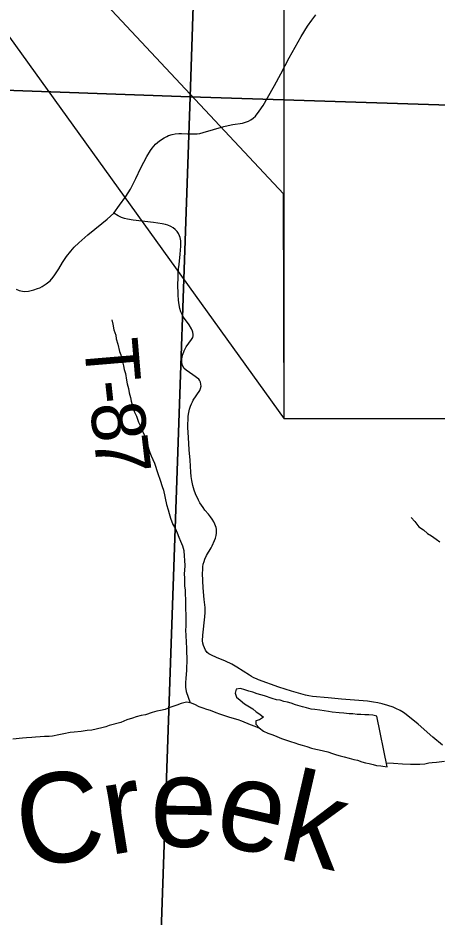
# Model space of a CAD drawing. Extents: x -3.3 to 34, y 0 to 56.8.
# Drawn here: x 0.477 to 0.92, y 29.768 to 30.716 of the extents above; entities that cross this region are included whole.
import ezdxf

# ---------------------------------------------------------------- set-up
doc = ezdxf.new("R2010")
doc.units = 0
for name, color, linetype in [('GM_X_Corporation', 7, 'Continuous'), ('GM_X_Township_Road', 7, 'Continuous'), ('GM_X_Township_Road_Text', 7, 'Continuous'), ('GT_Project_Cells', 7, 'Continuous'), ('GT_Project_Soil_Layers', 7, 'Continuous'), ('SH_Major_Grid_Line', 7, 'Continuous')]:
    doc.layers.add(name, color=color, linetype=linetype)

msp = doc.modelspace()

# ---------------------------------------------------------------- linework, layer by layer
at = {"layer": 'GM_X_Corporation'}
for points in [[(-0.3225, 31.67471), (0.6926, 31.6401), (0.65935, 30.63337), (-0.36109, 30.66979)], [(0.6926, 31.6401), (1.70556, 31.57323), (1.70222, 31.44962), (1.67669, 30.60068), (0.65935, 30.63337)], [(-0.36109, 30.66979), (0.65935, 30.63337), (0.62472, 29.64178), (-0.38619, 29.67495)], [(1.67669, 30.60068), (1.67248, 30.48389), (1.6376, 29.60296), (0.62472, 29.64178), (0.65935, 30.63337)]]:
    msp.add_lwpolyline(points, close=True, dxfattribs=at)
at = {"layer": 'GM_X_Township_Road'}
for points in [[(0.47554, 30.43026), (0.47865, 30.42902), (0.4821, 30.42823), (0.48443, 30.42801), (0.48865, 30.42824), (0.49418, 30.42962), (0.49799, 30.43092), (0.50047, 30.43194), (0.50293, 30.43315), (0.50712, 30.43583), (0.51135, 30.43931), (0.51443, 30.44293), (0.51618, 30.44538), (0.52042, 30.45199), (0.52432, 30.45852), (0.52853, 30.46469), (0.53314, 30.47056), (0.53683, 30.47476), (0.54148, 30.47938), (0.55118, 30.48783), (0.56589, 30.4997), (0.57139, 30.50419), (0.57509, 30.50737), (0.57867, 30.51058), (0.58474, 30.51882), (0.59122, 30.52799), (0.59633, 30.53598), (0.60186, 30.54709), (0.60724, 30.55842), (0.61347, 30.57017), (0.61745, 30.5768), (0.61905, 30.57909), (0.62249, 30.58329), (0.62677, 30.58689), (0.63173, 30.59013), (0.63453, 30.59158), (0.6364, 30.59237), (0.64026, 30.59358), (0.64328, 30.59418), (0.64721, 30.59447), (0.64998, 30.59454), (0.65653, 30.59421), (0.6626, 30.59408), (0.66656, 30.59426), (0.66932, 30.59471), (0.67292, 30.59561), (0.68391, 30.59885), (0.69489, 30.60209), (0.69947, 30.60305), (0.70406, 30.60391), (0.71427, 30.60548), (0.71775, 30.60639), (0.72061, 30.60763), (0.72317, 30.60909), (0.72552, 30.61077), (0.7281, 30.61295), (0.73209, 30.6183), (0.73626, 30.62417), (0.74097, 30.63208), (0.74811, 30.64518), (0.75475, 30.65737), (0.76373, 30.67431), (0.77649, 30.69678), (0.78309, 30.70772), (0.78755, 30.71427), (0.79175, 30.71967)], [(0.92568, 29.94955), (0.91532, 29.95793), (0.89978, 29.97142), (0.88727, 29.98162), (0.88423, 29.98384), (0.88093, 29.98584), (0.87639, 29.98818), (0.87342, 29.98946), (0.86799, 29.99138), (0.86184, 29.99308), (0.85736, 29.9941), (0.85281, 29.99487), (0.84635, 29.99567), (0.819, 29.99801), (0.80494, 29.99927), (0.7884, 30.00076), (0.78437, 30.00133), (0.78091, 30.00207), (0.76604, 30.00619), (0.75288, 30.01062), (0.73142, 30.0183), (0.72913, 30.01925), (0.72656, 30.0205), (0.72379, 30.02197), (0.72169, 30.02324), (0.70849, 30.03175), (0.70332, 30.03471), (0.69633, 30.03816), (0.68696, 30.04203), (0.68153, 30.04441), (0.67882, 30.04589), (0.6771, 30.04728), (0.67545, 30.04975), (0.67414, 30.05205), (0.67323, 30.0546), (0.67266, 30.05715), (0.67233, 30.05937), (0.67241, 30.06537), (0.67463, 30.08485), (0.67496, 30.08937), (0.67488, 30.09447), (0.67413, 30.10302), (0.67304, 30.11537), (0.67223, 30.13063), (0.67239, 30.13465), (0.67257, 30.13746), (0.67307, 30.14042), (0.67387, 30.14329), (0.67464, 30.14569), (0.67644, 30.1493), (0.68136, 30.15771), (0.68243, 30.15978), (0.68493, 30.16537), (0.68583, 30.16777), (0.68663, 30.17042), (0.68701, 30.17318), (0.68713, 30.17519), (0.68689, 30.17737), (0.68647, 30.179), (0.68527, 30.18245), (0.68415, 30.18485), (0.68233, 30.18791), (0.68081, 30.19017), (0.67859, 30.19304), (0.67478, 30.19742), (0.67273, 30.19999), (0.67101, 30.20242), (0.66935, 30.20509), (0.66791, 30.20774), (0.66474, 30.21458), (0.66341, 30.21853), (0.66212, 30.22332), (0.66108, 30.22859), (0.66033, 30.2329), (0.65992, 30.23738), (0.65901, 30.24984), (0.65821, 30.26084), (0.65725, 30.27406), (0.65686, 30.28461), (0.6572, 30.29628), (0.65778, 30.3003), (0.6586, 30.30367), (0.65961, 30.30702), (0.66049, 30.30951), (0.66149, 30.31159), (0.66244, 30.31333), (0.66924, 30.32339), (0.67021, 30.32559), (0.67065, 30.32803), (0.67057, 30.33024), (0.67001, 30.33243), (0.6692, 30.33434), (0.66847, 30.33536), (0.66182, 30.34017), (0.6549, 30.34494), (0.65288, 30.34685), (0.65145, 30.34929), (0.65079, 30.35106), (0.65032, 30.35348), (0.65025, 30.35474), (0.65038, 30.35679), (0.65069, 30.35875), (0.65145, 30.36163), (0.65274, 30.36517), (0.65512, 30.36955), (0.66076, 30.37719), (0.66193, 30.37956), (0.66228, 30.38103), (0.6624, 30.38253), (0.6621, 30.38502), (0.66173, 30.38617), (0.66067, 30.38847), (0.65811, 30.39276), (0.65424, 30.39788), (0.65191, 30.40119), (0.65056, 30.40361), (0.64933, 30.4064), (0.64817, 30.41011), (0.64744, 30.41393), (0.64693, 30.41884), (0.64652, 30.42451), (0.64627, 30.4361), (0.64635, 30.4412), (0.6466, 30.44605), (0.64693, 30.45172), (0.64742, 30.45649), (0.64853, 30.4674), (0.64931, 30.47572), (0.6494, 30.47852), (0.64923, 30.48145), (0.64851, 30.48494), (0.64796, 30.48665), (0.64698, 30.489), (0.64528, 30.49134), (0.64339, 30.4934), (0.6414, 30.49498), (0.6387, 30.49663), (0.63556, 30.49799), (0.633, 30.49872), (0.62965, 30.49935), (0.62038, 30.50063), (0.59904, 30.50332), (0.59313, 30.50418), (0.58989, 30.50495), (0.58669, 30.50611), (0.58316, 30.50787), (0.57867, 30.51058)]]:
    msp.add_lwpolyline(points, dxfattribs=at)
at = {"layer": 'GT_Project_Soil_Layers'}
for points in [[(0.57633, 30.39805), (0.57753, 30.39352), (0.57875, 30.38746), (0.58072, 30.3818), (0.58115, 30.37801), (0.58274, 30.37234), (0.58474, 30.36478), (0.58593, 30.361), (0.58713, 30.35646), (0.58874, 30.34966), (0.58955, 30.3455), (0.59074, 30.34134), (0.59197, 30.33453), (0.59279, 30.33036), (0.59399, 30.32545), (0.59481, 30.3209), (0.59601, 30.31599), (0.59682, 30.31221), (0.59841, 30.30691), (0.6004, 30.30049), (0.60235, 30.29635), (0.60471, 30.28993), (0.60666, 30.28578), (0.60823, 30.28201), (0.61058, 30.27673), (0.61177, 30.27257), (0.61374, 30.26691), (0.61651, 30.25822), (0.61808, 30.25445), (0.61965, 30.25067), (0.62159, 30.2469), (0.62515, 30.23595), (0.62752, 30.22877), (0.62951, 30.22235), (0.63108, 30.2182), (0.63432, 30.20307), (0.63591, 30.19778), (0.6371, 30.19362), (0.6383, 30.1887), (0.64104, 30.18229), (0.64337, 30.17815), (0.64534, 30.17324), (0.6473, 30.16872), (0.64887, 30.16457), (0.65121, 30.15967), (0.65241, 30.15475), (0.65287, 30.14868), (0.65331, 30.14452), (0.65339, 30.13845), (0.65275, 30.12971), (0.65318, 30.12592), (0.6533, 30.1172), (0.65373, 30.11341), (0.6538, 30.10772), (0.65423, 30.10393), (0.65461, 30.07586), (0.65431, 30.06978), (0.65474, 30.066), (0.65487, 30.05689), (0.6553, 30.05272), (0.65552, 30.03641), (0.65519, 30.03261), (0.65526, 30.02806), (0.6546, 30.02008), (0.65429, 30.01515), (0.65435, 30.01059), (0.6548, 30.00605), (0.65914, 29.99403)], [(0.89235, 30.18953), (0.8962, 30.1854), (0.90044, 30.17977), (0.90542, 30.17642), (0.90964, 30.17269), (0.91384, 30.17009), (0.91882, 30.16674), (0.92265, 30.16376)], [(0.86703, 29.92653), (0.85612, 29.97997), (0.85193, 29.98105), (0.84775, 29.98137), (0.84358, 29.98132), (0.83941, 29.98164), (0.83562, 29.98159), (0.83106, 29.98228), (0.82688, 29.9826), (0.82156, 29.98329), (0.81663, 29.9836), (0.80904, 29.98426), (0.80524, 29.98496), (0.80068, 29.98566), (0.79612, 29.98636), (0.7908, 29.98704), (0.787, 29.98737), (0.78205, 29.98882), (0.77787, 29.9899), (0.77026, 29.99207), (0.76569, 29.99353), (0.76188, 29.99462), (0.75808, 29.99532), (0.75426, 29.99679), (0.75047, 29.99711), (0.7459, 29.99857), (0.73752, 30.00149), (0.73371, 30.00258), (0.72991, 30.00366), (0.72533, 30.00512), (0.72115, 30.0062), (0.71696, 30.00766), (0.71239, 30.00911), (0.70785, 30.00829), (0.70677, 30.0041), (0.70796, 29.99995), (0.7118, 29.99696), (0.7164, 29.99285), (0.72022, 29.99101), (0.72519, 29.98766), (0.72902, 29.98468), (0.73285, 29.98208), (0.73668, 29.97909), (0.73255, 29.976), (0.72839, 29.97518), (0.72844, 29.97139), (0.73191, 29.96764), (0.7365, 29.96429), (0.74108, 29.96208), (0.74642, 29.96025), (0.75061, 29.95842), (0.75556, 29.95659), (0.76509, 29.9533), (0.76966, 29.95185), (0.77347, 29.95038), (0.77728, 29.94929), (0.78223, 29.94785), (0.78718, 29.94639), (0.79174, 29.94532), (0.79554, 29.94461), (0.80467, 29.94246), (0.80962, 29.94063), (0.81382, 29.93917), (0.81762, 29.93809), (0.82181, 29.937), (0.82714, 29.93556), (0.83208, 29.93411), (0.83589, 29.9334), (0.84046, 29.93195), (0.84426, 29.93086), (0.84806, 29.93016), (0.85225, 29.92907), (0.85606, 29.92799), (0.86061, 29.92767), (0.86703, 29.92653)], [(0.73278, 29.96701), (0.72772, 29.9691), (0.72276, 29.97093), (0.71361, 29.9746), (0.7098, 29.97607), (0.70105, 29.9786), (0.69457, 29.98079), (0.69038, 29.98225), (0.68657, 29.98334), (0.68047, 29.98591), (0.67666, 29.987), (0.67285, 29.98846), (0.66866, 29.98992), (0.66408, 29.99214), (0.65951, 29.99397), (0.65533, 29.99467), (0.64966, 29.99346), (0.64513, 29.9915), (0.63758, 29.98912), (0.63268, 29.98715), (0.62776, 29.98595), (0.62398, 29.98514), (0.61907, 29.98393), (0.6119, 29.98156), (0.60736, 29.98074), (0.60207, 29.97915), (0.5983, 29.97796), (0.59225, 29.97598), (0.58584, 29.97323), (0.57375, 29.97003), (0.56998, 29.96884), (0.56582, 29.96765), (0.55524, 29.96522), (0.55031, 29.96478), (0.54426, 29.96393), (0.53669, 29.96307), (0.53252, 29.96264), (0.52571, 29.9614), (0.52042, 29.96019), (0.51399, 29.95897), (0.5102, 29.95853), (0.50527, 29.95847), (0.50073, 29.95803), (0.4958, 29.95796), (0.49202, 29.95753), (0.48633, 29.95707), (0.48217, 29.95663), (0.47194, 29.95573)], [(0.92767, 29.932), (0.91934, 29.93113), (0.91479, 29.93069), (0.91101, 29.93026), (0.90685, 29.92944), (0.90155, 29.92899), (0.89169, 29.92885), (0.88334, 29.9295), (0.87385, 29.93013), (0.86627, 29.93028)]]:
    msp.add_lwpolyline(points, dxfattribs=at)
at = {"layer": 'SH_Major_Grid_Line'}
for points in [[(0.02177, 31.31596), (0.75855, 30.29376), (0.75776, 30.531)], [(0.75855, 30.86126), (2.29366, 30.86126), (2.29366, 30.29376), (0.75855, 30.29376)]]:
    msp.add_lwpolyline(points, close=True, dxfattribs=at)

# ---------------------------------------------------------------- texts
at = {"layer": 'GM_X_Township_Road_Text'}
for s, rotation, p in [('T', 274.80547, (0.54694, 30.37606)), ('-', 276.17277, (0.55064, 30.33224)), ('8', 276.52397, (0.55319, 30.30866)), ('7', 276.61859, (0.55718, 30.27379))]:
    msp.add_text(s, height=0.05682, rotation=rotation, dxfattribs=at).set_placement(p)
at = {"layer": 'GT_Project_Cells'}
for s, height, rotation, p in [('Cr', 0.094695, 8.9823, (0.48301, 29.81901)), ('ek', 0.094694, 346.9887, (0.68142, 29.84662)), ('e', 0.0947, 358.98513, (0.61632, 29.84281))]:
    msp.add_text(s, height=height, rotation=rotation, dxfattribs=at).set_placement(p)

doc.saveas('drawing.dxf')
